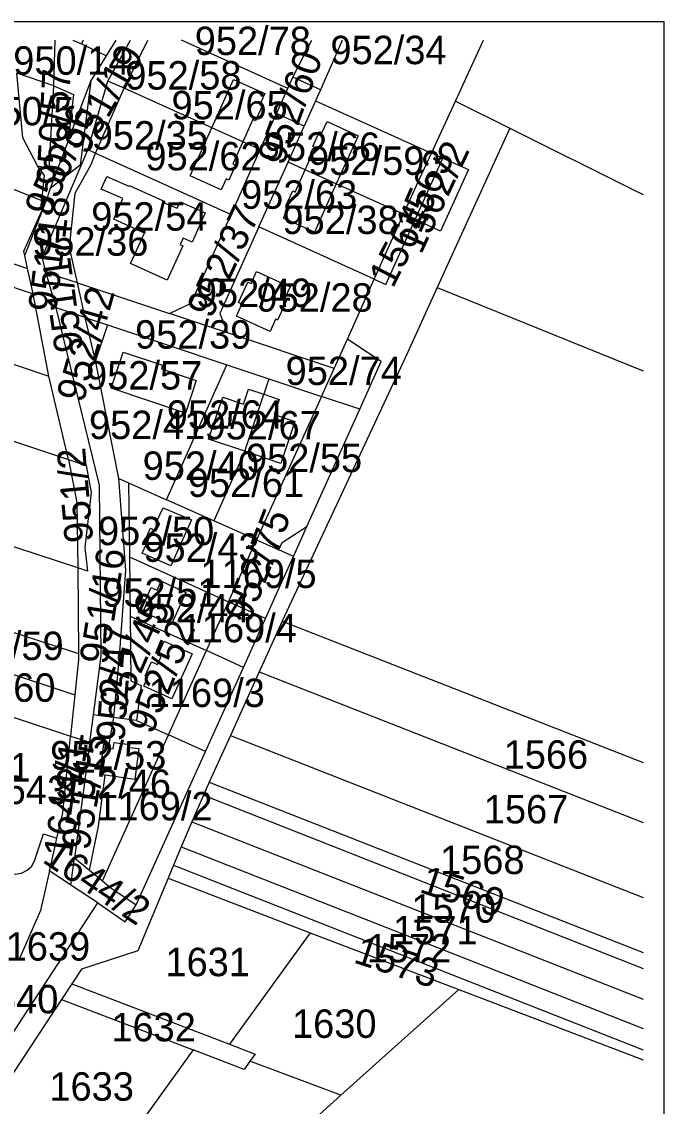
# Model space of a CAD drawing. Extents: x -583889 to -582839, y -1166553 to -1165068.
# Drawn here: x -582997 to -582838.7, y -1165334.9 to -1165067.8 of the extents above; entities that cross this region are included whole.
import ezdxf

# ---------------------------------------------------------------- set-up
doc = ezdxf.new("R2010")
doc.units = 0
for name, color, linetype in [('_parcely přehledka', 7, 'Continuous'), ('Hranice parcel', 7, 'Continuous'), ('Parcelní čísla', 7, 'Continuous')]:
    doc.layers.add(name, color=color, linetype=linetype)

msp = doc.modelspace()

# ---------------------------------------------------------------- linework, layer by layer
at = {"layer": '_parcely přehledka'}
msp.add_lwpolyline([(-583888.67, -1166552.78), (-582838.67, -1166552.78), (-582838.67, -1165067.78), (-583888.67, -1165067.78), (-583888.67, -1166552.78)], dxfattribs=at)
at = {"layer": 'Hranice parcel'}
for p, q in [((-582989.08, -1165083.58), (-582988.75, -1165072.33)), ((-582984.37, -1165072.33), (-582982.3, -1165073.19)), ((-582981.88, -1165072.33), (-582982.3, -1165073.19)), ((-582976.11, -1165076.18), (-582973.7, -1165072.33)), ((-582975.77, -1165082.41), (-582970.18, -1165072.33)), ((-582971.76, -1165084.12), (-582965.95, -1165072.33)), ((-582931.41, -1165084.2), (-582957.66, -1165072.33)), ((-582890.14, -1165087.34), (-582883.2, -1165072.33)), ((-582982.3, -1165073.19), (-582976.11, -1165076.18)), ((-582980.01, -1165082.44), (-582976.11, -1165076.18)), ((-582989.08, -1165083.58), (-582998.19, -1165080.46)), ((-582985.55, -1165097.11), (-582980.01, -1165082.44)), ((-582980.74, -1165099.31), (-582975.77, -1165082.41)), ((-582971.76, -1165084.12), (-582975.77, -1165082.41)), ((-582950.17, -1165093.88), (-582944.82, -1165082)), ((-582931.41, -1165084.2), (-582930.18, -1165081.47)), ((-582923.35, -1165084.56), (-582930.18, -1165081.47)), ((-582978.82, -1165100.16), (-582971.76, -1165084.12)), ((-582950.17, -1165093.88), (-582971.76, -1165084.12)), ((-582934.2, -1165090.39), (-582931.41, -1165084.2)), ((-582923.35, -1165084.56), (-582924.6, -1165087.3)), ((-582924.6, -1165087.3), (-582927.38, -1165093.47)), ((-582924.6, -1165087.3), (-582896.05, -1165100.12)), ((-582896.05, -1165100.12), (-582890.14, -1165087.34)), ((-582890.14, -1165087.34), (-582876.77, -1165094.03)), ((-583044.73, -1165091.1), (-582992.03, -1165111.81)), ((-582938.21, -1165099.29), (-582934.2, -1165090.39)), ((-582927.38, -1165093.47), (-582934.2, -1165090.39)), ((-582955.52, -1165105.74), (-582950.17, -1165093.88)), ((-582942.51, -1165097.35), (-582950.17, -1165093.88)), ((-582940.04, -1165091.86), (-582942.51, -1165097.35)), ((-582931.38, -1165102.35), (-582927.38, -1165093.47)), ((-582876.77, -1165094.03), (-582894.67, -1165133.25)), ((-582985.55, -1165097.11), (-582989.97, -1165108.83)), ((-582978.82, -1165100.16), (-582980.74, -1165099.31)), ((-582945.4, -1165115.24), (-582938.21, -1165099.29)), ((-582942.51, -1165097.35), (-582944.97, -1165102.81)), ((-582938.21, -1165099.29), (-582942.51, -1165097.35)), ((-582978.82, -1165100.16), (-582945.4, -1165115.24)), ((-582938.58, -1165118.32), (-582931.38, -1165102.35)), ((-582927.13, -1165104.27), (-582931.38, -1165102.35)), ((-582900.07, -1165116.51), (-582893.22, -1165101.39)), ((-582893.22, -1165101.39), (-582896.05, -1165100.12)), ((-582919.49, -1165107.73), (-582927.13, -1165104.27)), ((-582902.93, -1165115.22), (-582919.49, -1165107.73)), ((-583050.67, -1165110.17), (-582995.55, -1165128.53)), ((-582989.97, -1165108.83), (-582991.1, -1165112.18)), ((-582996.24, -1165125.39), (-582991.1, -1165112.18)), ((-582991.1, -1165112.18), (-582992.03, -1165111.81)), ((-583052.33, -1165115.41), (-582994.16, -1165134.79)), ((-582910.14, -1165131.21), (-582902.93, -1165115.22)), ((-582902.93, -1165115.22), (-582900.07, -1165116.51)), ((-582910.14, -1165131.21), (-582938.58, -1165118.32)), ((-582995.55, -1165128.53), (-582996.24, -1165125.39)), ((-582994.16, -1165134.79), (-582995.55, -1165128.53)), ((-582983.24, -1165132.1), (-582990.97, -1165129.61)), ((-582988.54, -1165138.25), (-582990.97, -1165129.61)), ((-582916.77, -1165145.93), (-582910.14, -1165131.21)), ((-583057.74, -1165132.59), (-582990.33, -1165155.04)), ((-582983.24, -1165132.1), (-582960.56, -1165139.67)), ((-582981.35, -1165140.64), (-582983.24, -1165132.1)), ((-582894.67, -1165133.25), (-582843.89, -1165153.75)), ((-582990.33, -1165155.04), (-582994.16, -1165134.79)), ((-582981.35, -1165140.64), (-582988.54, -1165138.25)), ((-582946.28, -1165144.37), (-582960.56, -1165139.67)), ((-582981.35, -1165140.64), (-582975.89, -1165142.46)), ((-582978.82, -1165151.26), (-582981.35, -1165140.64)), ((-582975.89, -1165142.46), (-582978.82, -1165151.26)), ((-582975.89, -1165142.46), (-582946.46, -1165152.25)), ((-582920.02, -1165153.15), (-582946.28, -1165144.37)), ((-582920.02, -1165153.15), (-582916.77, -1165145.93)), ((-582973.05, -1165180.25), (-582978.82, -1165151.26)), ((-582961.29, -1165185.52), (-582946.46, -1165152.25)), ((-582946.46, -1165152.25), (-582936.08, -1165155.72)), ((-582923.13, -1165160.05), (-582920.02, -1165153.15)), ((-582985.47, -1165175.64), (-582990.33, -1165155.04)), ((-582936.08, -1165155.72), (-582937.36, -1165159.55)), ((-582936.08, -1165155.72), (-582923.13, -1165160.05)), ((-582942.04, -1165173.58), (-582937.36, -1165159.55)), ((-582923.13, -1165160.05), (-582939.16, -1165195.39)), ((-582913.72, -1165163.2), (-582923.13, -1165160.05)), ((-582926.73, -1165192.11), (-582913.72, -1165163.2)), ((-583019.35, -1165164.35), (-582985.47, -1165175.64)), ((-582942.04, -1165173.58), (-582949.68, -1165190.7)), ((-582973.05, -1165180.25), (-582970.66, -1165181.34)), ((-582970.66, -1165181.34), (-582961.29, -1165185.52)), ((-582970.66, -1165181.34), (-582970.47, -1165199.6)), ((-582983.21, -1165202.31), (-583027.19, -1165187.87)), ((-582949.68, -1165190.7), (-582961.29, -1165185.52)), ((-582939.16, -1165195.39), (-582949.68, -1165190.7)), ((-582930.03, -1165199.46), (-582926.73, -1165192.11)), ((-582946.05, -1165210.63), (-582939.16, -1165195.39)), ((-582939.16, -1165195.39), (-582933.68, -1165197.83)), ((-582930.03, -1165199.46), (-582933.68, -1165197.83)), ((-582970.47, -1165199.6), (-582946.05, -1165210.63)), ((-582970.47, -1165199.6), (-582970.31, -1165214.18)), ((-582983.21, -1165202.31), (-582983.03, -1165223.42)), ((-582951.49, -1165222.68), (-582946.05, -1165210.63)), ((-582936.94, -1165214.75), (-582946.05, -1165210.63)), ((-583014.39, -1165213.12), (-582983.03, -1165223.42)), ((-582970.31, -1165214.18), (-582951.49, -1165222.68)), ((-582942.38, -1165226.8), (-582936.94, -1165214.75)), ((-582932.83, -1165215.38), (-582938.52, -1165227.88)), ((-582932.83, -1165215.38), (-582843.89, -1165250.24)), ((-583017.5, -1165222.52), (-582983.91, -1165233.54)), ((-582960.85, -1165243.41), (-582951.49, -1165222.68)), ((-582942.38, -1165226.8), (-582951.49, -1165222.68)), ((-582983.02, -1165224.92), (-582983.91, -1165233.54)), ((-582983.03, -1165223.42), (-582983.02, -1165224.92)), ((-582951.73, -1165247.52), (-582942.38, -1165226.8)), ((-582938.52, -1165227.88), (-582945.59, -1165243.55)), ((-582938.52, -1165227.88), (-582843.89, -1165264.98)), ((-582983.91, -1165233.54), (-582984.95, -1165243.7)), ((-582980.23, -1165245.22), (-582979.33, -1165238.45)), ((-582974.34, -1165239.11), (-582979.33, -1165238.45)), ((-582999.09, -1165239.08), (-582984.95, -1165243.7)), ((-582975.63, -1165246.73), (-582974.34, -1165239.11)), ((-582968.73, -1165239.86), (-582974.34, -1165239.11)), ((-582968.73, -1165239.86), (-582960.85, -1165243.41)), ((-582984.95, -1165243.7), (-582980.23, -1165245.22)), ((-582977.1, -1165279.37), (-582960.85, -1165243.41)), ((-582951.73, -1165247.52), (-582960.85, -1165243.41)), ((-582945.59, -1165243.55), (-582950.78, -1165255.07)), ((-582945.59, -1165243.55), (-582843.89, -1165283.5)), ((-582980.23, -1165245.22), (-582984, -1165273.74)), ((-582976.53, -1165246.61), (-582975.63, -1165246.73)), ((-582975.63, -1165246.73), (-582974.43, -1165246.89)), ((-582968.78, -1165285.24), (-582951.73, -1165247.52)), ((-582976.47, -1165253.37), (-582977.75, -1165253.2)), ((-582969.12, -1165254.38), (-582976.47, -1165253.37)), ((-582950.78, -1165255.07), (-582952.24, -1165258.31)), ((-582950.78, -1165255.07), (-582843.89, -1165297.05)), ((-582952.24, -1165258.31), (-582955.06, -1165264.82)), ((-582952.24, -1165258.31), (-582843.89, -1165300.92)), ((-582955.06, -1165264.82), (-582957.7, -1165270.97)), ((-582955.06, -1165264.82), (-582843.89, -1165308.55)), ((-582957.7, -1165270.97), (-582959.57, -1165275.47)), ((-582984.89, -1165280.42), (-582984, -1165273.74)), ((-582984, -1165273.74), (-582980.28, -1165276.78)), ((-582959.57, -1165275.47), (-582960.94, -1165278.74)), ((-582959.57, -1165275.47), (-582843.89, -1165320.95)), ((-582984.89, -1165280.42), (-582990.16, -1165276.9)), ((-582980.28, -1165276.78), (-582977.1, -1165279.37)), ((-582960.94, -1165278.74), (-582925.93, -1165292.14)), ((-582978.28, -1165284.82), (-582984.89, -1165280.42)), ((-583000.42, -1165318.79), (-582978.28, -1165284.82)), ((-582925.93, -1165292.14), (-582945.82, -1165319.61)), ((-582925.93, -1165292.14), (-582889.34, -1165306.14)), ((-582984.67, -1165304.74), (-582987.21, -1165308.59)), ((-582984.67, -1165304.74), (-582945.82, -1165319.61)), ((-582889.34, -1165306.14), (-582918.34, -1165332.17)), ((-582889.34, -1165306.14), (-582843.89, -1165323.47)), ((-582987.21, -1165308.59), (-583007.11, -1165338.81)), ((-582987.21, -1165308.59), (-582954.72, -1165321.03)), ((-582954.72, -1165321.03), (-582976.18, -1165350.65)), ((-582918.34, -1165332.17), (-582940.77, -1165323.79)), ((-582918.34, -1165332.17), (-582950.06, -1165360.65))]:
    msp.add_line(p, q, dxfattribs=at)
for points in [[(-582930.18, -1165081.47), (-582925.54, -1165072.33)], [(-582918.12, -1165072.33), (-582918.14, -1165072.56), (-582923.35, -1165084.56)], [(-582993.15, -1165103.26), (-582996.72, -1165096.42), (-582998.19, -1165080.46)], [(-582993.15, -1165103.26), (-582990.23, -1165103.85), (-582989.08, -1165083.58)], [(-582980.01, -1165082.44), (-582982.56, -1165103.14), (-582989.97, -1165108.83)], [(-582989.08, -1165083.58), (-582984.25, -1165085.74), (-582985.55, -1165097.11)], [(-582944.82, -1165082), (-582937.12, -1165085.44), (-582938.36, -1165088.19), (-582937.74, -1165088.47), (-582939.41, -1165092.16), (-582940.04, -1165091.86)], [(-582927.13, -1165104.27), (-582924.66, -1165098.8), (-582925.31, -1165098.51), (-582923.65, -1165094.83), (-582923.02, -1165095.14), (-582921.75, -1165092.39), (-582914.14, -1165095.87), (-582919.49, -1165107.73)], [(-582876.77, -1165094.03), (-582846.07, -1165109.29), (-582843.89, -1165110.31)], [(-582990.97, -1165129.61), (-582991.96, -1165125.8), (-582980.74, -1165099.31)], [(-582983.24, -1165132.1), (-582985.25, -1165123.41), (-582983.85, -1165110.01), (-582979.89, -1165102.93), (-582978.82, -1165100.16)], [(-582902.93, -1165115.22), (-582898.92, -1165106.32), (-582896.05, -1165100.12)], [(-582893.22, -1165101.39), (-582886.92, -1165104.22), (-582893.81, -1165119.33), (-582900.07, -1165116.51)], [(-582992.03, -1165111.81), (-582991.4, -1165105.65), (-582993.15, -1165103.26)], [(-582944.97, -1165102.81), (-582944.34, -1165103.1), (-582945.98, -1165106.78), (-582946.64, -1165106.48), (-582947.87, -1165109.21), (-582955.52, -1165105.74)], [(-582919.49, -1165107.73), (-582924.84, -1165119.61), (-582932.5, -1165116.15), (-582931.26, -1165113.41), (-582931.9, -1165113.12), (-582930.24, -1165109.44), (-582929.6, -1165109.74), (-582927.13, -1165104.27)], [(-582966.79, -1165119.85), (-582974.34, -1165116.44), (-582972.09, -1165111.35), (-582977.39, -1165109), (-582975.99, -1165105.9), (-582970.6, -1165108.3), (-582970.5, -1165108.08), (-582961.72, -1165112.05), (-582961.87, -1165112.38), (-582958.7, -1165113.74), (-582957.96, -1165112.11), (-582951.8, -1165114.89), (-582955.02, -1165122.06), (-582957.22, -1165121.09), (-582957.96, -1165122.66), (-582957.3, -1165122.94), (-582961.15, -1165131.41), (-582970.17, -1165127.32), (-582966.79, -1165119.85)], [(-582996.24, -1165125.39), (-582996.48, -1165124.32), (-582991.1, -1165112.18)], [(-582960.56, -1165139.67), (-582955.22, -1165137.06), (-582945.4, -1165115.24)], [(-582938.58, -1165118.32), (-582948.17, -1165139.62), (-582946.28, -1165144.37)], [(-582910.14, -1165131.21), (-582907.32, -1165132.49), (-582900.07, -1165116.51)], [(-582940.47, -1165132.28), (-582939.12, -1165129.28), (-582930.89, -1165133.05), (-582932.24, -1165136.04), (-582931.68, -1165136.3), (-582933.97, -1165141.32), (-582934.5, -1165141.04), (-582935.81, -1165144.05), (-582944.11, -1165140.3), (-582942.74, -1165137.31), (-582943.56, -1165136.93), (-582941.28, -1165131.9), (-582940.47, -1165132.28)], [(-582894.67, -1165133.25), (-582901.99, -1165149.31), (-582932.83, -1165215.38)], [(-582979.33, -1165238.45), (-582977.41, -1165223.93), (-582977.85, -1165181.94), (-582988.54, -1165138.25)], [(-582913.72, -1165163.2), (-582908.46, -1165151.5), (-582914.89, -1165147.19), (-582916.77, -1165145.93)], [(-582974.99, -1165158.05), (-582972.04, -1165149.13), (-582962.28, -1165152.37), (-582962.57, -1165153.3), (-582954.03, -1165156.15), (-582956.68, -1165164.16), (-582974.99, -1165158.05)], [(-582942.04, -1165173.58), (-582950.96, -1165170.59), (-582947.49, -1165160.26), (-582942.37, -1165161.98), (-582941.12, -1165158.29), (-582937.36, -1165159.55)], [(-582937.36, -1165159.55), (-582933.61, -1165160.8), (-582934.8, -1165164.5), (-582929.7, -1165166.23), (-582933.17, -1165176.55), (-582942.04, -1165173.58)], [(-582985.47, -1165175.64), (-582983.42, -1165186.22), (-582983.21, -1165202.31)], [(-582985.47, -1165175.64), (-582981.1, -1165177.09), (-582979.9, -1165183.76), (-582981.45, -1165197.3), (-582980.83, -1165203.08), (-582983.21, -1165202.31)], [(-582974.34, -1165239.11), (-582972.87, -1165224.02), (-582971.36, -1165202.84), (-582973.05, -1165180.25)], [(-582955.15, -1165190.49), (-582960.24, -1165201.83), (-582967.3, -1165198.63), (-582966.22, -1165196.34), (-582966.87, -1165196.06), (-582965.26, -1165192.53), (-582963.88, -1165193.14), (-582963.01, -1165191.38), (-582963.83, -1165190.95), (-582962.18, -1165187.47), (-582955.15, -1165190.49)], [(-582933.68, -1165197.83), (-582932.87, -1165196.01), (-582926.73, -1165192.11)], [(-582936.94, -1165214.75), (-582933.14, -1165206.34), (-582930.03, -1165199.46)], [(-582966.06, -1165210.82), (-582966.68, -1165210.54), (-582965.13, -1165207.15), (-582963.63, -1165207.79), (-582962.77, -1165205.86), (-582963.59, -1165205.48), (-582963.45, -1165205.17), (-582956.54, -1165208.35), (-582960.16, -1165216.31), (-582967.06, -1165213.11), (-582966.06, -1165210.82)], [(-582970.31, -1165214.18), (-582970.15, -1165230.11), (-582967.59, -1165231.27), (-582968.73, -1165239.86)], [(-582965, -1165225.47), (-582963.54, -1165226.12), (-582962.62, -1165224.12), (-582963.46, -1165223.76), (-582961.94, -1165220.34), (-582955, -1165223.49), (-582960, -1165234.55), (-582966.93, -1165231.41), (-582965.9, -1165229.13), (-582966.55, -1165228.87), (-582965, -1165225.47)], [(-582988.32, -1165268.87), (-582987.64, -1165265.86), (-582986.89, -1165262.6), (-582984.95, -1165243.7)], [(-582977.75, -1165253.2), (-582976.76, -1165245.68), (-582976.42, -1165245.73), (-582976.53, -1165246.61)], [(-582974.43, -1165246.89), (-582974.21, -1165245.31), (-582970.46, -1165245.81), (-582970.54, -1165246.49), (-582968.13, -1165246.78), (-582969.12, -1165254.38)], [(-582980.28, -1165276.78), (-582978.11, -1165265.9), (-582976.47, -1165253.37)], [(-583010.51, -1165274.01), (-583001.61, -1165276.92), (-583000.06, -1165277.42), (-582998.56, -1165277.7), (-582997.02, -1165277.49), (-582995.62, -1165276.78), (-582994.54, -1165275.76), (-582993.75, -1165274.23), (-582991.64, -1165267.79), (-582988.32, -1165268.87)], [(-582990.16, -1165276.9), (-582989.11, -1165272.32), (-582988.32, -1165268.87)], [(-582957.7, -1165270.97), (-582882.68, -1165300.48), (-582843.89, -1165315.74)], [(-582990.16, -1165276.9), (-582992.4, -1165286.65), (-582997.54, -1165298.5)], [(-582960.94, -1165278.74), (-582968.43, -1165296.62), (-582982.31, -1165301.15), (-582984.67, -1165304.74)], [(-582977.1, -1165279.37), (-582975.28, -1165280.91), (-582968.78, -1165285.24)], [(-582978.28, -1165284.82), (-582971.52, -1165289.44), (-582968.78, -1165285.24)], [(-582940.77, -1165323.79), (-582942.23, -1165325.81), (-582954.72, -1165321.03)], [(-582945.82, -1165319.61), (-582939.49, -1165322.02), (-582940.77, -1165323.79)]]:
    msp.add_lwpolyline(points, dxfattribs=at)

# ---------------------------------------------------------------- texts
at = {"layer": 'Parcelní čísla'}
for s, p in [('952/78', (-582954.38, -1165075.99)), ('952/34', (-582920.95, -1165078.24)), ('950/14', (-582999.09, -1165080.84)), ('952/58', (-582971.48, -1165084.49)), ('950/5', (-583007.4, -1165093.31)), ('952/65', (-582960.09, -1165091.81)), ('952/35', (-582979.76, -1165099.27)), ('952/62', (-582966.53, -1165104.41)), ('952/66', (-582937.35, -1165102.05)), ('952/59', (-582926.41, -1165105.51)), ('952/63', (-582942.97, -1165113.86)), ('952/54', (-582979.87, -1165119.24)), ('952/38', (-582932.75, -1165120.08)), ('952/36', (-582994.43, -1165125.42)), ('952/49', (-582954.09, -1165138.04)), ('952/28', (-582939.16, -1165139.19)), ('952/39', (-582969.06, -1165148.3)), ('952/74', (-582931.98, -1165157.26)), ('952/57', (-582981.15, -1165158.37)), ('952/64', (-582961.25, -1165168.03)), ('952/41', (-582980.43, -1165170.57)), ('952/67', (-582951.95, -1165170.66)), ('952/55', (-582941.75, -1165178.72)), ('952/40', (-582967.21, -1165180.62)), ('952/61', (-582956.06, -1165184.82)), ('952/50', (-582978.21, -1165196.69)), ('952/43', (-582967.03, -1165200.82)), ('1169/5', (-582952.97, -1165207.25)), ('952/51', (-582977.16, -1165211.83)), ('952/44', (-582969.46, -1165215.74)), ('1169/4', (-582957.83, -1165220.62)), ('950/59', (-583015.29, -1165225)), ('950/60', (-583017.32, -1165235.27)), ('1169/3', (-582965.72, -1165236.56)), ('952/53', (-582990, -1165251.95)), ('1566', (-582878.26, -1165251.75)), ('1645/1', (-583023.47, -1165254.92)), ('952/46', (-582988.86, -1165258.96)), ('1643', (-583006.41, -1165260.47)), ('1169/2', (-582978.62, -1165264.47)), ('1567', (-582883.15, -1165265.23)), ('1568', (-582893.94, -1165277.69)), ('1570', (-582900.99, -1165289.69)), ('1571', (-582905.5, -1165294.99)), ('1639', (-583000.96, -1165299.02)), ('1572', (-582912.01, -1165299.45)), ('1631', (-582961.59, -1165302.85)), ('1640', (-583008.79, -1165312.01)), ('1632', (-582974.92, -1165318.89)), ('1630', (-582930.41, -1165318.05)), ('1633', (-582990.19, -1165333.51))]:
    msp.add_text(s, height=7, dxfattribs=at).set_placement(p)
for s, rotation, p in [('951/19', 60, (-582981, -1165100.86)), ('952/60', 70, (-582932.55, -1165103.52)), ('950/57', 87, (-582986.4, -1165108.18)), ('950/36', 66, (-582990.23, -1165116.38)), ('1563', 66, (-582898.79, -1165120.24)), ('1562/2', 65, (-582898.59, -1165125.32)), ('951/18', 83, (-582988.53, -1165139.51)), ('952/37', 65, (-582950.29, -1165141.17)), ('1564', 63, (-582905.56, -1165133.64)), ('951/17', 98, (-582981.83, -1165148.69)), ('952/42', 74, (-582981.86, -1165161.86)), ('951/2', 95, (-582979.36, -1165195.79)), ('952/75', 69, (-582940.85, -1165216.23)), ('951/16', 81, (-582975.93, -1165226.3)), ('952/45', 66, (-582971.94, -1165238.21)), ('952/47', 86, (-582971.7, -1165245.2)), ('952/52', 68, (-582964.82, -1165243.58)), ('951/15', 80, (-582980.4, -1165272.06)), ('1644/1', 82, (-582984.7, -1165273.87)), ('1644/2', 326, (-582992.2, -1165274.6)), ('1569', 342, (-582899.3, -1165282.09)), ('1573', 342, (-582915.52, -1165299.42))]:
    msp.add_text(s, height=7, rotation=rotation, dxfattribs=at).set_placement(p)

doc.saveas('drawing.dxf')
